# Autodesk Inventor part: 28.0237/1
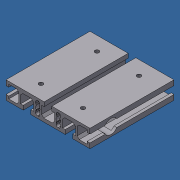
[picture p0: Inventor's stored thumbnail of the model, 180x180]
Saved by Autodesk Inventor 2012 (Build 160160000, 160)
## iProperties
Created: 2007-06
Part Number: 28.0237/1
Material: Aluminum-6061
Document SubType Name: Modeling
Designer: Andy Moles
Density: 2.71 g/cm^3
Description: SLIDE LWN-S WITH TOP CLAMP 90X19
Stock Number: 20.0995 PROFILE 90 X 19
Mass: 162.6 g
Surface Area: 452.499 cm^2
Volume: 60.0002 cm^3
Author: Andy Moles
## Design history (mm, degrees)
sketch "Sketch1"
  geometry: L1 (18.4, -9.5)-(18.4, -5) reference; L2 (17.9, -5)-(15.7, -5) reference; L3 (15.7, -5)-(15.7, 3.5) reference; L4 (15.7, 3.5)-(18, 5.8) reference; L5 (18, 5.8)-(27, 5.8) reference; L6 (27, 5.8)-(29.3, 3.5) reference; L7 (29.3, 3.5)-(29.3, -5) reference; L8 (26.6, -5)-(26.6, -9.5) reference; L9 (45, -9.5)-(26.9, -9.5) reference; L10 (45, -4.1)-(45, -9.5) reference; L11 (45, -4.1)-(42, -4.1) reference; L12 (42, -4.6)-(42, -6.8) reference; L13 (42, -6.8)-(33.5, -6.8) reference; L14 (33.5, -6.8)-(31.2, -4.5) reference; L15 (31.2, -4.5)-(31.2, 4.5) reference; L16 (31.2, 4.5)-(33.5, 6.8) reference; L17 (33.5, 6.8)-(42, 6.8) reference; L18 (42, 4.1)-(45, 4.1) reference; L19 (45, 9.5)-(45, 4.1) reference; L20 (4.4, 9.5)-(45, 9.5) reference; L21 (4.1, 9.5)-(4.1, 5) reference; L22 (4.6, 5)-(6.8, 5) reference; L23 (6.8, 5)-(6.8, -3.5) reference; L24 (6.8, -3.5)-(4.5, -5.8) reference; L25 (4.5, -5.8)-(-4.5, -5.8) reference; L26 (-4.5, -5.8)-(-6.8, -3.5) reference; L27 (-6.8, -3.5)-(-6.8, 5) reference; L28 (-4.1, 5)-(-4.1, 9.5) reference; L29 (-45, 4.1)-(-45, 9.5) reference; L30 (-45, 4.1)-(-42, 4.1) reference; L31 (-42, 4.1)-(-42, 6.8) reference; L32 (-42, 6.8)-(-33.5, 6.8) reference; L33 (-33.5, 6.8)-(-31.2, 4.5) reference; L34 (-31.2, 4.5)-(-31.2, -4.5) reference; L35 (-31.2, -4.5)-(-33.5, -6.8) reference; L36 (-33.5, -6.8)-(-42, -6.8) reference; L37 (-42, -6.8)-(-42, -4.1) reference; L38 (-42, -4.1)-(-45, -4.1) reference; L39 (-45, -9.5)-(-45, -4.1) reference; L40 (-26.6, -9.5)-(-26.6, -5) reference; L41 (-29.3, -5)-(-29.3, 3.5) reference; L42 (-29.3, 3.5)-(-27, 5.8) reference; L43 (-27, 5.8)-(-18, 5.8) reference; L44 (-18, 5.8)-(-15.7, 3.5) reference; L45 (-15.7, 3.5)-(-15.7, -5) reference; L46 (-15.7, -5)-(-17.9, -5) reference; L47 (-18.4, -5)-(-18.4, -9.5) reference; L48 (-18.1, -9.5)-(-18.4, -9.5) reference; L49 (-26.6, -9.5)-(-45, -9.5) reference; L50 (-17.9, -5)-(-18.4, -5) reference; L51 (-26.6, -5)-(-29.3, -5) reference; L52 (-6.8, 5)-(-4.1, 5) reference; L53 (4.1, 5)-(4.6, 5) reference; L54 (-45, 9.5)-(-4.1, 9.5) reference; L55 (4.1, 9.5)-(4.4, 9.5) reference; L56 (29.3, -5)-(26.6, -5) reference; L57 (18.4, -5)-(17.9, -5) reference; L58 (26.9, -9.5)-(26.6, -9.5) reference; L59 (18.4, -9.5)-(-18.1, -9.5) reference; L60 (42, 6.8)-(42, 4.1) reference; L61 (42, -4.1)-(42, -4.6) reference; L62 (-9.354, -2.59)-(-8.993, -2.95); L63 (-10.7, -7)-(-11.3, -7); L64 (-8.7, -3.657)-(-8.7, -5)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; A1 r 2.5 centre (-11, 0) between (-9.333, -1.863) and (-9.333, 1.863); A2 r 1 centre (-9.7, -3.657) between (-8.7, -3.657) and (-8.993, -2.95); A3 r 2 centre (-10.7, -5) between (-10.7, -7) and (-8.7, -5); A4 r 0.5 centre (-9, -2.236) between (-9.333, -1.863) and (-9.354, -2.59); A5 r 1 centre (-12.3, -3.657) between (-13.007, -2.95) and (-13.3, -3.657); A6 r 2.5 centre (-11, 0) between (-12.667, 1.863) and (-12.667, -1.863); A7 r 2 centre (-11.3, -5) between (-13.3, -5) and (-11.3, -7); A8 r 0.5 centre (-13, -2.236) between (-12.646, -2.59) and (-12.667, -1.863); A9 r 0.5 centre (-13, 2.236) between (-12.667, 1.863) and (-12.646, 2.59); A10 r 2 centre (-11.3, 5) between (-11.3, 7) and (-13.3, 5); A11 r 0.5 centre (-9, 2.236) between (-9.354, 2.59) and (-9.333, 1.863); A12 r 1 centre (-9.7, 3.657) between (-8.993, 2.95) and (-8.7, 3.657); A13 r 2 centre (-10.7, 5) between (-8.7, 5) and (-10.7, 7); A14 r 1 centre (-12.3, 3.657) between (-13.3, 3.657) and (-13.007, 2.95); A15 r 1 centre (12.3, 3.657) between (13.007, 2.95) and (13.3, 3.657); A16 r 0.5 centre (13, 2.236) between (12.646, 2.59) and (12.667, 1.863); A17 r 2 centre (11.3, 5) between (13.3, 5) and (11.3, 7); A18 r 0.5 centre (9, 2.236) between (9.333, 1.863) and (9.354, 2.59); A19 r 1 centre (9.7, 3.657) between (8.7, 3.657) and (8.993, 2.95); A20 r 2 centre (10.7, 5) between (10.7, 7) and (8.7, 5); A21 r 1 centre (9.7, -3.657) between (8.993, -2.95) and (8.7, -3.657); A22 r 2.5 centre (11, 0) between (9.333, 1.863) and (9.333, -1.863); A23 r 0.5 centre (9, -2.236) between (9.354, -2.59) and (9.333, -1.863); A24 r 2 centre (10.7, -5) between (8.7, -5) and (10.7, -7); A25 r 2.5 centre (11, 0) between (12.667, -1.863) and (12.667, 1.863); A26 r 0.5 centre (13, -2.236) between (12.667, -1.863) and (12.646, -2.59); A27 r 1 centre (12.3, -3.657) between (13.3, -3.657) and (13.007, -2.95); A28 r 2 centre (11.3, -5) between (11.3, -7) and (13.3, -5)
  constraints: 162 end point, 56 point on circle, 28 centre point, 28 horizontal, 23 vertical, 71 other
extrude "Extrusion1" new body sketch "Sketch1" stored distance "d0" = 90; taper "d1" = 0 deg
sketch "Sketch2"
  geometry: L1 (-26.6, -90)-(-26.6, 0) reference; L2 (63.4, -90)-(63.4, 0) reference; L3 (-8.2, 0)-(-26.6, 0) reference; L4 (-26.6, -90)-(-8.2, -90) reference; 5 further points
  constraints: 2 horizontal alignment, 2 vertical alignment
  dimensions: "d2" = 22.5 distance from line of point (-4.1, -15) L1; "d3" = 22.5 distance from line of point (40.9, -15) L2; "d4" = 15 distance from line of point (-4.1, -15) L3; "d5" = 15 distance from line of point (-4.1, -75) L4
hole "Hole1" sketch "Sketch2" at (40.9, -15), (40.9, -75), (-4.1, -75), (-4.1, -15) diameter "d6" = 4.5; stored, may be unused: countersink angle "d10" = 90 deg, drill point angle "d12" = 118 deg; dims "d7" = 6, "d8" = 4, "d9" = 2, "d11" = 4.5
sketch "Sketch3"
  geometry: L1 (0, 5.4)-(0, 0) reference; L2 (0, 0.4)-(0, -8.6) reference; 3 further points
  constraints: 1 horizontal alignment, 1 midpoint
  dimensions: "d13" = 22.5 distance from line of point (22.5, -4.1) L1
hole "Hole2" sketch "Sketch3" at (22.5, -4.1) diameter "d14" = 15; stored, may be unused: countersink angle "d18" = 90 deg, drill point angle "d20" = 0 deg; dims "d15" = 6, "d16" = 4, "d17" = 2, "d19" = 16
sketch "Sketch4"
  geometry: C1 r 7.5 at (-22.5, -4.1); A1 r 7.5 centre (-22.5, -4.1) between (-28.78, -8.2) and (-16.22, -8.2) reference; 1 further point
  constraints: 1 centre point, 1 coincident, 1 concentric
extrude "Extrusion2" cut sketch "Sketch4" distance "d21" = 16; taper "d22" = 0 deg
body "Solid1"
